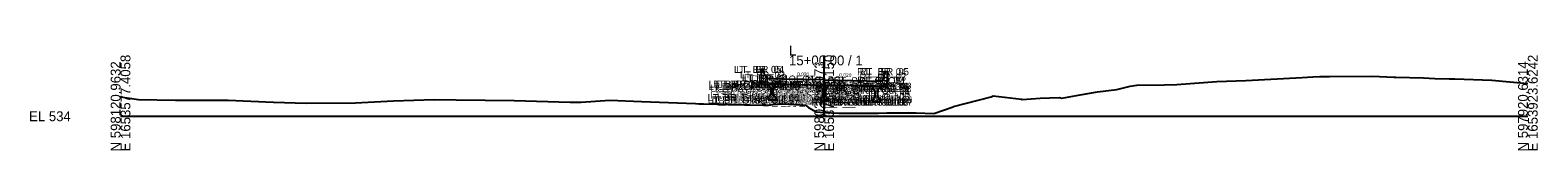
# Model space of a CAD drawing. Extents: x -26 to 403, y -10 to 6021.
# Drawn here: x -25.7 to 402.8, y 3490.3 to 3520.1 of the extents above; entities that cross this region are included whole.
import ezdxf

# ---------------------------------------------------------------- set-up
doc = ezdxf.new("R2010")
doc.units = 0
for name, color, linetype in [('Default', 7, 'Continuous'), ('Exist Cross Section Cell', 7, 'Continuous'), ('Exist XS Ground Line', 7, 'Continuous'), ('Prop CMT Concrete Structures', 7, 'Continuous'), ('Prop XS SE Text', 7, 'Continuous')]:
    doc.layers.add(name, color=color, linetype=linetype)

msp = doc.modelspace()

# ---------------------------------------------------------------- linework, layer by layer
at = {"layer": 'Exist Cross Section Cell'}
for p, q in [((200, 3500), (200, 3517.26)), ((0, 3500), (200, 3500)), ((200, 3500), (400, 3500))]:
    msp.add_line(p, q, dxfattribs=at)
at = {"layer": 'Exist XS Ground Line'}
msp.add_lwpolyline([(0, 3505.51), (5.07, 3504.73), (15.63, 3504.61), (18.3, 3504.55), (30.56, 3504.56), (43.45, 3503.96), (52.77, 3503.72), (66.78, 3503.8), (77.6, 3504.36), (89.12, 3504.72), (95.35, 3504.64), (111.86, 3504.44), (127.84, 3504.04), (129.65, 3503.99), (130.92, 3504.01), (139.07, 3504.53), (148.04, 3504.21), (163.43, 3503.59), (164.39, 3503.55), (164.85, 3503.54), (165.73, 3503.52), (177.31, 3503.27), (178.85, 3503.24), (182.73, 3503.14), (184.21, 3503.15), (185.5, 3503.31), (188.32, 3503.48), (194.71, 3503.19), (195.57, 3502.5), (197.71, 3501.22), (200, 3501.08), (204.09, 3500.84), (215.41, 3500.87), (217.8, 3500.98), (218.91, 3500.98), (226.14, 3500.97), (231.2, 3500.75), (236.68, 3502.72), (236.73, 3502.75), (247.47, 3505.52), (248.06, 3505.77), (256.06, 3504.81), (256.25, 3504.79), (261.39, 3505.16), (266.85, 3505.37), (267.51, 3505.18), (272.74, 3506.08), (277.67, 3506.98), (283.22, 3507.6), (286.93, 3508.55), (288.86, 3508.84), (296.73, 3508.89), (300.27, 3508.98), (311.57, 3509.84), (319.85, 3510.18), (335.82, 3511.03), (338.85, 3511.21), (340.87, 3511.33), (343.62, 3511.34), (355.81, 3511.41), (361.89, 3511.14), (362.05, 3511.14), (362.43, 3511.13), (370.33, 3510.92), (373.54, 3510.77), (377.6, 3510.66), (378.21, 3510.68), (379.21, 3510.65), (389.78, 3510.21), (400, 3509.26)], dxfattribs=at)
at = {"layer": 'Prop CMT Concrete Structures'}
for points in [[(200, 3510.33), (188, 3510.57), (183.58, 3510.66), (183.57, 3510.91), (182.99, 3511.74), (182.82, 3513.32), (182.08, 3513.32), (182.08, 3509.19)], [(200, 3510.33), (212, 3510.09), (216.42, 3510), (216.43, 3510.25), (217.01, 3511.08), (217.18, 3512.67), (217.92, 3512.67), (217.92, 3508.47)], [(200, 3508.83), (200, 3510.33)], [(200, 3508.83), (200, 3510.33)], [(182.08, 3509.19), (188, 3509.07), (200, 3508.83)], [(184.87, 3506.04), (184.12, 3505.29)], [(186.04, 3509.11), (185.21, 3509.12), (184.37, 3509.14)], [(184.37, 3509.14), (184.37, 3508.46)], [(184.37, 3508.46), (184.87, 3507.96)], [(184.87, 3507.96), (184.87, 3506.04)], [(185.54, 3507.96), (186.04, 3508.46)], [(185.54, 3506.04), (185.54, 3507.96)], [(186.29, 3505.29), (185.54, 3506.04)], [(186.04, 3508.46), (186.04, 3509.11)], [(199.67, 3505.74), (198.92, 3504.99)], [(200, 3508.83), (199.17, 3508.84)], [(199.17, 3508.84), (199.17, 3508.16)], [(199.17, 3508.16), (199.67, 3507.66)], [(199.67, 3507.66), (199.67, 3505.74)], [(217.92, 3508.47), (212, 3508.59), (200, 3508.83)], [(200, 3504.33), (200, 3508.83)], [(200, 3508.83), (200.83, 3508.81)], [(200, 3504.33), (200, 3508.83)], [(200.83, 3508.16), (200.33, 3507.66)], [(200.33, 3507.66), (200.33, 3505.74)], [(200.33, 3505.74), (201.08, 3504.99)], [(200.83, 3508.81), (200.83, 3508.16)], [(213.71, 3504.7), (214.46, 3505.45)], [(213.96, 3508.55), (214.79, 3508.53), (215.63, 3508.51)], [(213.96, 3507.86), (213.96, 3508.55)], [(214.46, 3507.36), (213.96, 3507.86)], [(214.46, 3505.45), (214.46, 3507.36)], [(215.63, 3507.86), (215.13, 3507.36)], [(215.13, 3507.36), (215.13, 3505.45)], [(215.13, 3505.45), (215.88, 3504.7)], [(215.63, 3508.51), (215.63, 3507.86)], [(184.12, 3505.29), (184.12, 3504.62)], [(184.12, 3504.62), (185.21, 3504.62), (186.29, 3504.62)], [(186.29, 3504.62), (186.29, 3505.29)], [(198.92, 3504.99), (198.92, 3504.33)], [(198.92, 3504.33), (200, 3504.33)], [(201.08, 3504.33), (200, 3504.33)], [(201.08, 3504.99), (201.08, 3504.33)], [(213.71, 3504.03), (213.71, 3504.7)], [(215.88, 3504.03), (214.79, 3504.03), (213.71, 3504.03)], [(215.88, 3504.7), (215.88, 3504.03)]]:
    msp.add_lwpolyline(points, dxfattribs=at)

# ---------------------------------------------------------------- texts
at = {"layer": 'Default'}
for s, height, p in [('LT_ BR_05', 2, (174.32, 3512.32)), ('LT_ BR_04', 2, (175.06, 3512.32)), ('LT_BR_Girder Out 02', 2, (167.16, 3508.14)), ('LT_BR_Girder Out 01', 2, (168.56, 3508.12)), ('LT_BR_Girder Out 14', 2, (169.47, 3508.11)), ('LT_BR_06', 2, (175.09, 3508.19)), ('LT_BR_03', 2, (176.05, 3510.74)), ('LT_BR_02', 2, (176.63, 3509.91)), ('LT_BR_01', 2, (177.21, 3509.66)), ('LT_PV1_OEOT', 2, (178.74, 3509.57)), ('LT_BR_07', 2, (181.06, 3508.07)), ('LT_BR_Girder Mid 02', 2, (182.35, 3507.84)), ('RT_BR_Girder Mid 02', 2, (183.97, 3507.81)), ('PV1_PGL', 2, (194.47, 3509.33)), ('BR_PGL', 2, (194.83, 3507.83)), ('RT_PV1_OEOT', 2, (202.69, 3509.09)), ('RT_ BR_04', 2, (209.37, 3511.67)), ('RT_BR_02', 2, (209.43, 3509.25)), ('RT_BR_01', 2, (209.99, 3509)), ('RT_BR_03', 2, (210.02, 3510.08)), ('RT_ BR_05', 2, (210.11, 3511.67)), ('LT_BR_Girder Out 06', 2, (166.86, 3504.29)), ('LT_BR_Girder Out 07', 2, (166.91, 3503.62)), ('LT_BR_Girder Out 03', 2, (167.16, 3507.46)), ('LT_BR_Girder Out 04', 2, (167.66, 3506.96)), ('LT_BR_Girder Out 05', 2, (167.66, 3505.04)), ('LT_BR_Girder Out 08', 2, (167.99, 3503.62)), ('LT_BR_Girder Out 12', 2, (168.97, 3506.96)), ('LT_BR_Girder Out 09', 2, (169.08, 3503.62)), ('LT_BR_Girder Out 13', 2, (169.47, 3507.46)), ('LT_BR_Girder Out 11', 2, (169.54, 3505.04)), ('LT_BR_Girder Out 10', 2, (169.64, 3504.29)), ('LT_BR_Girder Mid 06', 2, (182.05, 3503.99)), ('LT_BR_Girder Mid 07', 2, (182.1, 3503.33)), ('LT_BR_Girder Mid 03', 2, (182.35, 3507.16)), ('LT_BR_Girder Mid 04', 2, (182.85, 3506.66)), ('LT_BR_Girder Mid 05', 2, (182.85, 3504.74)), ('RT_BR_Girder Mid 04', 2, (183.47, 3506.66)), ('RT_BR_Girder Mid 05', 2, (183.47, 3504.74)), ('RT_BR_Girder Mid 03', 2, (183.97, 3507.16)), ('RT_BR_Girder Mid 06', 2, (184.17, 3503.99)), ('RT_BR_Girder Mid 07', 2, (184.22, 3503.33)), ('BR_Girder Mid 08', 2, (185.87, 3503.33)), ('RT_BR_Girder Out 10', 2, (197.02, 3503.7)), ('RT_BR_Girder Out 14', 2, (197.35, 3507.55)), ('RT_BR_Girder Out 13', 2, (197.35, 3506.86)), ('RT_BR_Girder Out 12', 2, (197.85, 3506.36)), ('RT_BR_Girder Out 04', 2, (197.87, 3506.36)), ('RT_BR_Girder Out 05', 2, (197.87, 3504.45)), ('RT_BR_Girder Out 01', 2, (198.1, 3507.53)), ('RT_BR_Girder Out 02', 2, (198.37, 3507.51)), ('RT_BR_Girder Out 03', 2, (198.37, 3506.86)), ('RT_BR_Girder Out 11', 2, (198.41, 3504.45)), ('RT_BR_Girder Out 06', 2, (198.57, 3503.7)), ('RT_BR_07', 2, (205.01, 3507.59)), ('RT_BR_06', 2, (210.88, 3507.47)), ('RT_BR_Girder Out 09', 2, (196.45, 3503.03)), ('RT_BR_Girder Out 08', 2, (197.53, 3503.03)), ('RT_BR_Girder Out 07', 2, (198.62, 3503.03)), ('-', 0.0001, (0, 3500))]:
    msp.add_text(s, height=height, dxfattribs=at).set_placement(p)
at = {"layer": 'Exist Cross Section Cell'}
for s, p in [('L', (190, 3517.26)), ('15+00.00 / 1', (190, 3514.46)), ('EL 534', (-26, 3498.6))]:
    msp.add_text(s, height=2.8, dxfattribs=at).set_placement(p)
for s, p in [('N 598120.9632', (0, 3490)), ('E 1653577.4058', (2.8, 3490)), ('N 598020.7973', (200, 3490)), ('E 1653750.5150', (202.8, 3490)), ('N 597920.6314', (400, 3490)), ('E 1653923.6242', (402.8, 3490))]:
    msp.add_text(s, height=2.8, rotation=90, dxfattribs=at).set_placement(p)
at = {"layer": 'Prop XS SE Text'}
for p in [(192.27, 3511.48), (204.27, 3511.24)]:
    msp.add_text('0.020', height=1, rotation=358.8542, dxfattribs=at).set_placement(p)

doc.saveas('drawing.dxf')
